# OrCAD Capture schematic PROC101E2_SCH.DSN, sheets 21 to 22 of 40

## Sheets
21 14.OSPI: size C; title: OSPI
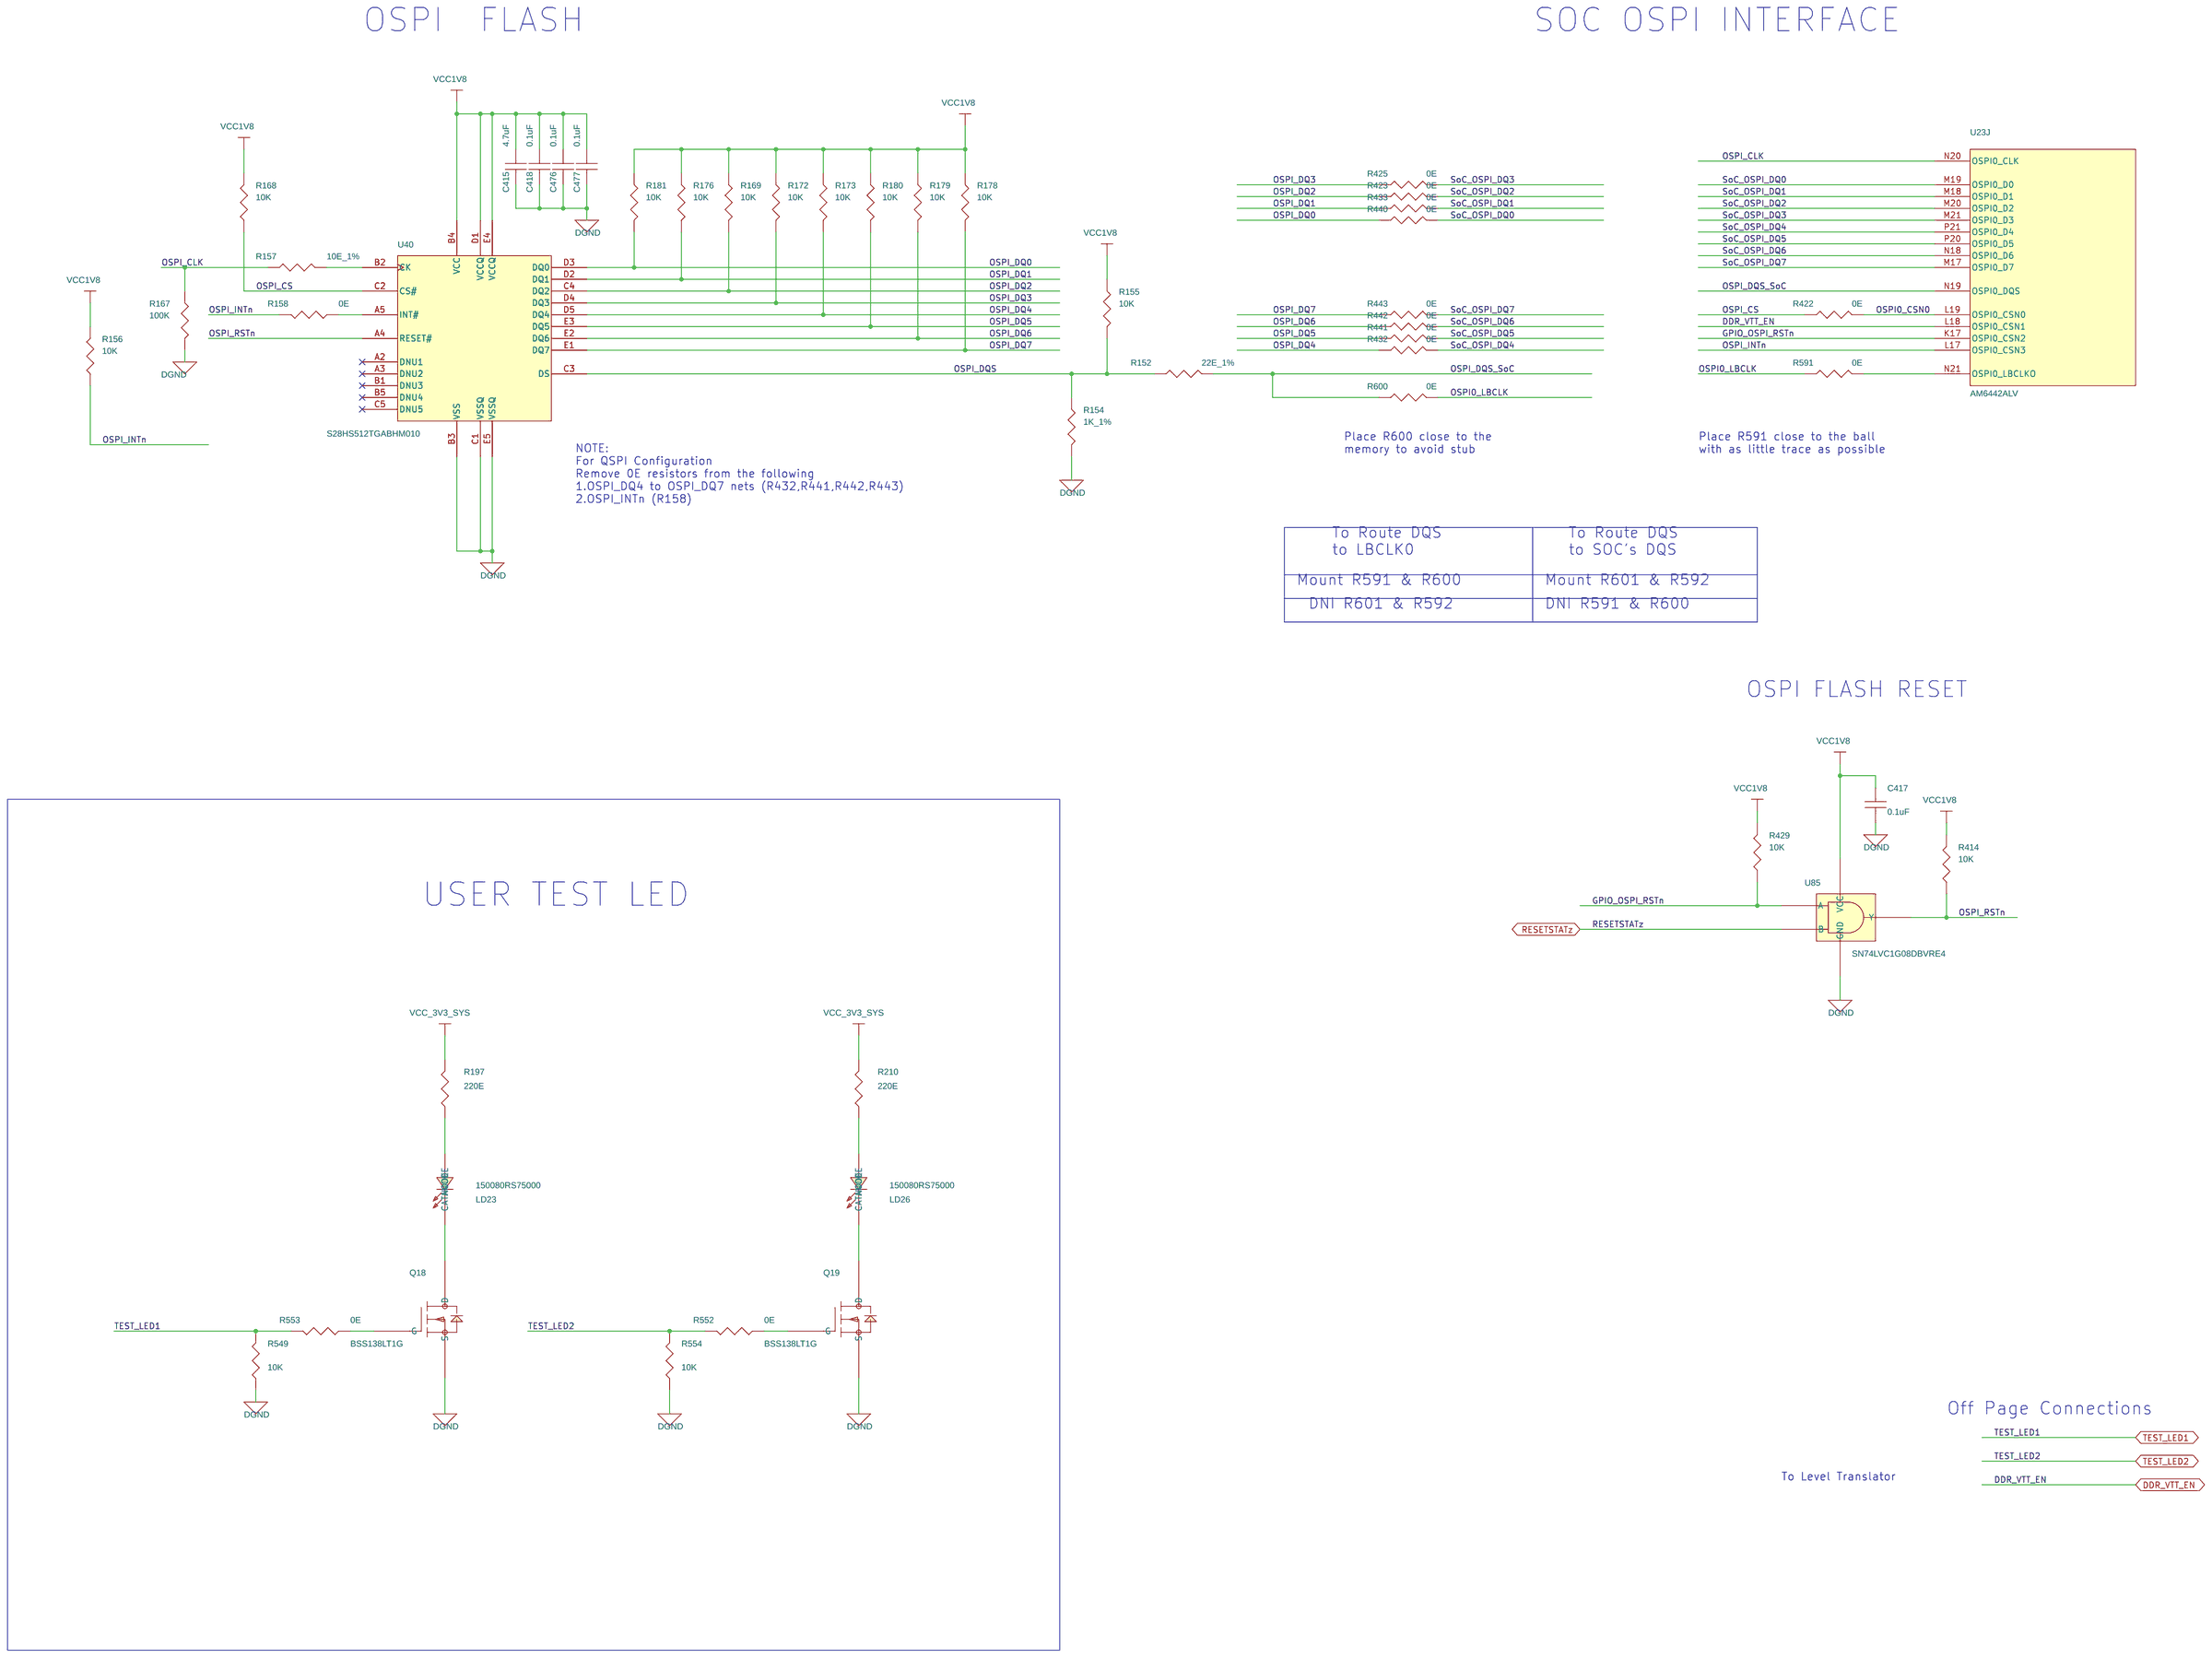
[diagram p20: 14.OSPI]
22 12.DDR INTERFACE: size C; title: DDR INTERFACE
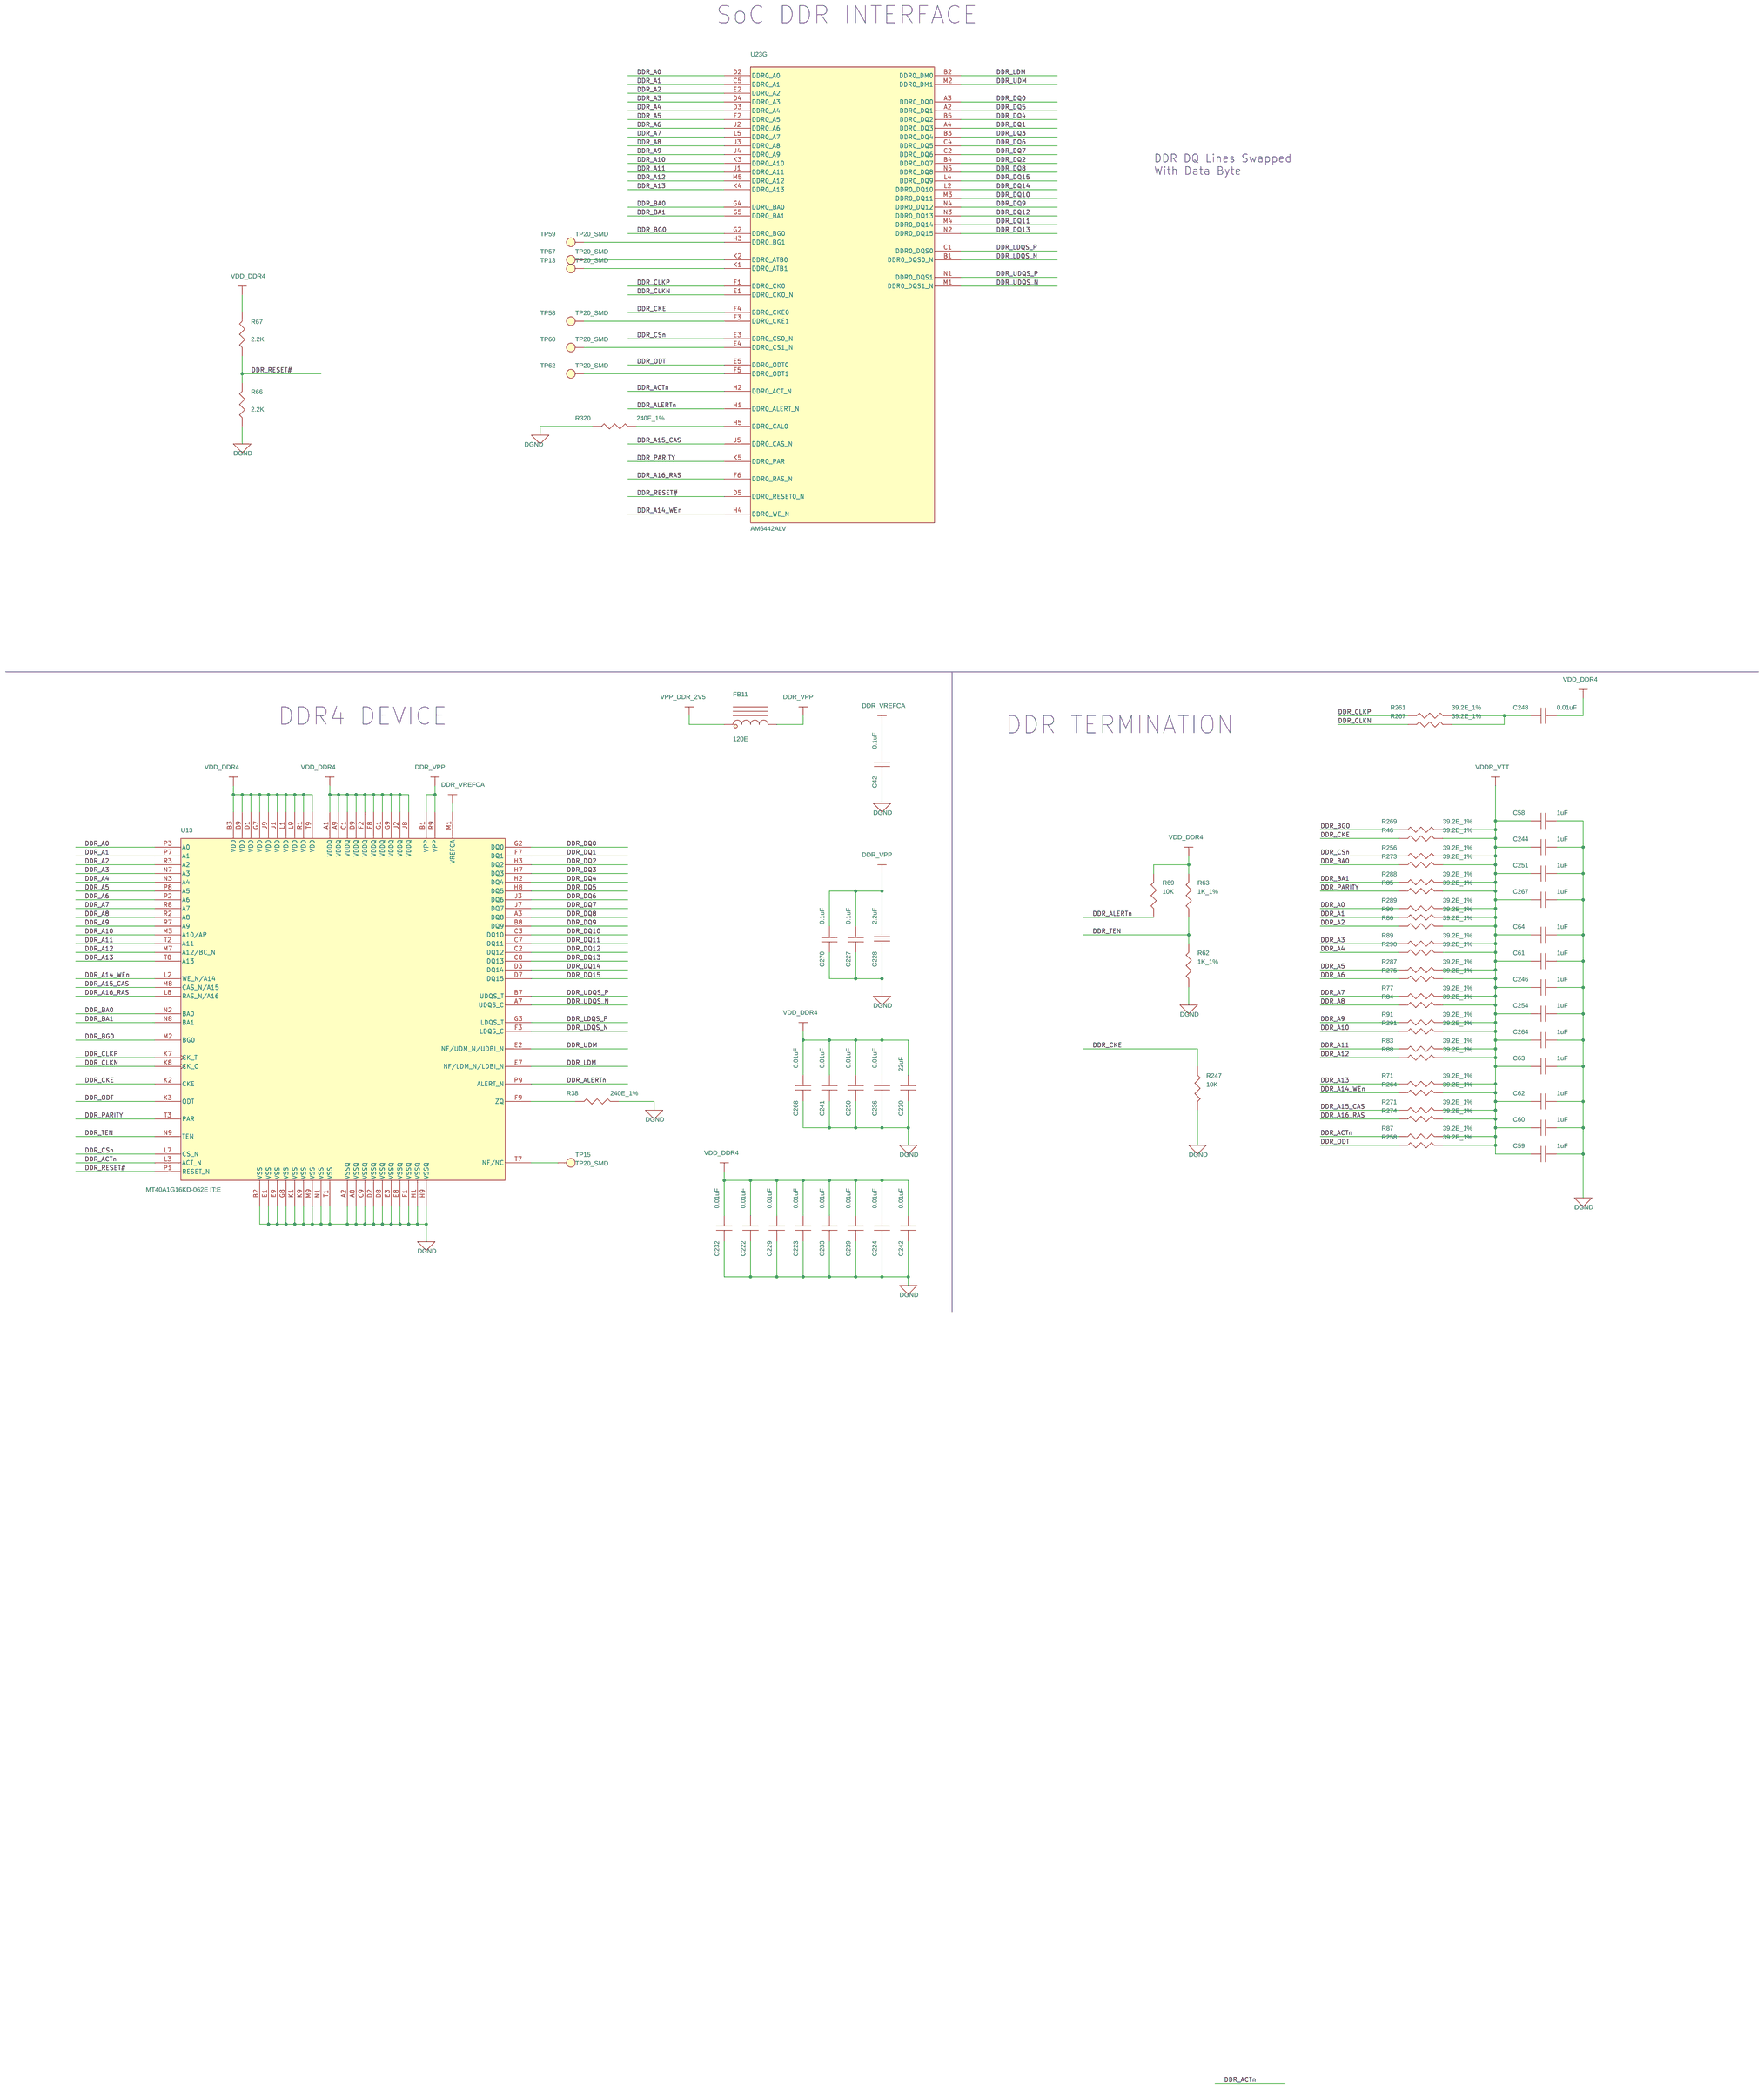
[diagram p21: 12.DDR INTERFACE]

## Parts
sheet 11.SOC VSS
U23  AM6442ALV  [FCBGA441_31-49_680X680_2-6]  (sections A,B,C,D,E,F,G,H,I,J,K,L,M,N,O,P)
sheet 12.DDR INTERFACE
C42  0.1uF  [CAP0201_0-5]
C58  1uF  [CAP0402_0-75]
C59  1uF  [CAP0402_0-75]
C60  1uF  [CAP0402_0-75]
C61  1uF  [CAP0402_0-75]
C62  1uF  [CAP0402_0-75]
C63  1uF  [CAP0402_0-75]
C64  1uF  [CAP0402_0-75]
C222  0.01uF  [CAP0201_0-5]
C223  0.01uF  [CAP0201_0-5]
C224  0.01uF  [CAP0201_0-5]
C227  0.1uF  [CAP0201_0-5]
C228  2.2uF  [CAP0402_0-75]
C229  0.01uF  [CAP0201_0-5]
C230  22uF  [CAP0603_1]
C232  0.01uF  [CAP0201_0-5]
C233  0.01uF  [CAP0201_0-5]
C236  0.01uF  [CAP0201_0-5]
C239  0.01uF  [CAP0201_0-5]
C241  0.01uF  [CAP0201_0-5]
C242  0.01uF  [CAP0201_0-5]
C244  1uF  [CAP0402_0-75]
C246  1uF  [CAP0402_0-75]
C248  0.01uF  [CAP0201_0-5]
C250  0.01uF  [CAP0201_0-5]
C251  1uF  [CAP0402_0-75]
C254  1uF  [CAP0402_0-75]
C264  1uF  [CAP0402_0-75]
C267  1uF  [CAP0402_0-75]
C268  0.01uF  [CAP0201_0-5]
C270  0.1uF  [CAP0201_0-5]
FB11  120E  [IND0603_1]
R38  240E_1%  [RES0402_0-5]
R46  39.2E_1%  [RES0402_0-5]
R62  1K_1%  [RES0402_0-5]
R63  1K_1%  [RES0402_0-5]
R66  2.2K  [RES0402_0-5]
R67  2.2K  [RES0402_0-5]
R69  10K  [RES0402_0-5]
R71  39.2E_1%  [RES0402_0-5]
R77  39.2E_1%  [RES0402_0-5]
R83  39.2E_1%  [RES0402_0-5]
R84  39.2E_1%  [RES0402_0-5]
R85  39.2E_1%  [RES0402_0-5]
R86  39.2E_1%  [RES0402_0-5]
R87  39.2E_1%  [RES0402_0-5]
R88  39.2E_1%  [RES0402_0-5]
R89  39.2E_1%  [RES0402_0-5]
R90  39.2E_1%  [RES0402_0-5]
R91  39.2E_1%  [RES0402_0-5]
R247  10K  [RES0402_0-5]
R256  39.2E_1%  [RES0402_0-5]
R258  39.2E_1%  [RES0402_0-5]
R261  39.2E_1%  [RES0402_0-5]
R264  39.2E_1%  [RES0402_0-5]
R267  39.2E_1%  [RES0402_0-5]
R269  39.2E_1%  [RES0402_0-5]
R271  39.2E_1%  [RES0402_0-5]
R273  39.2E_1%  [RES0402_0-5]
R274  39.2E_1%  [RES0402_0-5]
R275  39.2E_1%  [RES0402_0-5]
R287  39.2E_1%  [RES0402_0-5]
R288  39.2E_1%  [RES0402_0-5]
R289  39.2E_1%  [RES0402_0-5]
R290  39.2E_1%  [RES0402_0-5]
R291  39.2E_1%  [RES0402_0-5]
R320  240E_1%  [RES0402_0-5]
TP13  TP20_SMD  [TP20_SMD]
TP15  TP20_SMD  [TP20_SMD]
TP57  TP20_SMD  [TP20_SMD]
TP58  TP20_SMD  [TP20_SMD]
TP59  TP20_SMD  [TP20_SMD]
TP60  TP20_SMD  [TP20_SMD]
TP62  TP20_SMD  [TP20_SMD]
U13  MT40A1G16KD-062E IT:E  [FBGA96_31-49_520X360_1-2]
sheet 14.OSPI
C415  4.7uF  [CAP0402_0-75]
C417  0.1uF  [CAP0402_0-75]
C418  0.1uF  [CAP0402_0-75]
C476  0.1uF  [CAP0402_0-75]
C477  0.1uF  [CAP0402_0-75]
LD23  150080RS75000  [LED_150080VS75000_80X50_SMD_0-8]
LD26  150080RS75000  [LED_150080VS75000_80X50_SMD_0-8]
Q18  BSS138LT1G  [SOT23-123_1-2]
Q19  BSS138LT1G  [SOT23-123_1-2]
R152  22E_1%  [RES0402_0-5]
R154  1K_1%  [RES0402_0-5]
R155  10K  [RES0402_0-5]
R156  10K  [RES0402_0-5]
R157  10E_1%  [RES0402_0-5]
R158  0E  [RES0402_0-5]
R167  100K  [RES0402_0-5]
R168  10K  [RES0402_0-5]
R169  10K  [RES0402_0-5]
R172  10K  [RES0402_0-5]
R173  10K  [RES0402_0-5]
R176  10K  [RES0402_0-5]
R178  10K  [RES0402_0-5]
R179  10K  [RES0402_0-5]
R180  10K  [RES0402_0-5]
R181  10K  [RES0402_0-5]
R197  220E  [RES0402_0-5]
R210  220E  [RES0402_0-5]
R414  10K  [RES0402_0-5]
R422  0E  [RES0402_0-5]
R423  0E  [RES0402_0-5]
R425  0E  [RES0402_0-5]
R429  10K  [RES0402_0-5]
R432  0E  [RES0402_0-5]
R433  0E  [RES0402_0-5]
R440  0E  [RES0402_0-5]
R441  0E  [RES0402_0-5]
R442  0E  [RES0402_0-5]
R443  0E  [RES0402_0-5]
R549  10K  [RES0402_0-5]
R552  0E  [RES0402_0-5]
R553  0E  [RES0402_0-5]
R554  10K  [RES0402_0-5]
R591  0E  [RES0402_0-5]
R600  0E  [RES0402_0-5]
U40  S28HS512TGABHM010  [BGA24_39-37_240X310_1]
U85  SN74LVC1G08DBVRE4  [SOT23-5]

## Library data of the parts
U23 = AM64-SVB_BGA441: IC AM64 SoC MICROPROCESSOR BGA441; Chkd/date: MANIRAJA/020520; Crtd /date: ALVY/090420; Custom_Duty: 15%; Customs_HS_Code: 85423100; Distributor_name: NA; Distributor_part_number: NA; Footprint Path: Y:\MIS_DATABASE\Library\ALTIUM_TOOL\PCB_FOOTPRINTS\Altium_Footprint_Lib.PcbLib; Height: 2.57MM; Library Path: Y:\MIS_DATABASE\Library\ALTIUM_TOOL\SCHEMATICS_PARTS\MS_MICROPROCESSOR_Library.schlib; Mfr_name: TEXAS INSTRUMENTS; Mfr_part_number: AM6442ASFGGAALV; Mistral Part No: 141220040002; Package: BGA441; Part_type: ICS\DIGITAL\MICROPROCESSOR; Project: AM64x_SVB BRD; RoHS: NA; Temperature: NA; Tolerance: NA; Voltage: NA; Wattage: NA; Weight: NA; Datasheet: Y:\MIS_DATABASE\DATASHEETS\ICS\DIGITAL\MICROCONTROLLER\AM64-SoC_SVB.PDF
C42 C227 C270 = CAP: CAP CERAMIC 0.1uF 16V 10% X5R 0201; Chkd/date: MANIRAJA/120218; Crtd /date: MANIRAJA/120218; Custom_Duty: 15%; Customs_HS_Code: 85322990; Distributor_name: DIGIKEY; Distributor_part_number: 490-16742-1-ND; Footprint Path: Y:\MIS_DATABASE\Library\ALTIUM_TOOL\PCB_FOOTPRINTS\Altium_Footprint_Lib.PcbLib; Height: 0.33MM; Library Path: Y:\MIS_DATABASE\Library\ALTIUM_TOOL\SCHEMATICS_PARTS\MS_DISCRETE_Library.schlib; Mfr_name: MURATA; Mfr_part_number: GRM033R61C104KE84J; Mistral Part No: 120009030072-R; Package: 0201; Part_type: CAPACITORS\CERAMIC; Project: TI_MAXIE_CPB; RoHS: RoHS; Temperature: -55°C+85°C; Tolerance: 10%; Voltage: 16V; Wattage: NA; Weight: 0.33mg; Datasheet: Y:\MIS_DATABASE\DATASHEETS\CAPACITORS\GRM033R61C104KE84.PDF
C58-C64 C244 C246 C251 C254 C264 C267 = CAP: CAP CERAMIC 1uF 10V 20% X5R 0402; Chkd/date: MANIRAJA/210820; Crtd /date: ALVY/190820; Custom_Duty: 15%; Customs_HS_Code: 85322990; Distributor_name: DIGIKEY; Distributor_part_number: 732-7489-1-ND; Footprint Path: Y:\MIS_DATABASE\Library\ALTIUM_TOOL\PCB_FOOTPRINTS\Altium_Footprint_Lib.PcbLib; Height: 0.55MM; Library Path: Y:\MIS_DATABASE\Library\ALTIUM_TOOL\SCHEMATICS_PARTS\MS_DISCRETE_Library.schlib; Mfr_name: WURTH ELECTRONICS; Mfr_part_number: 885012105012; Mistral Part No: 120020080009-R; Package: 0402; Part_type: CAPACITORS\CERAMIC; Project: AM64x_EVM_BRD; RoHS: RoHS; Temperature: -55°C+85°C; Tolerance: 20%; Voltage: 10V; Wattage: NA; Weight: 0.65mg; Datasheet: Y:\MIS_DATABASE\DATASHEETS\CAPACITORS\885012105012.PDF
C222-C224 C229 C232 C233 C236 C239 C241 C242 C248 C250 C268 = CAP: CAP CERAMIC 0.01uF 25V 10% X5R 0201; Chkd/date: MANIRAJA/230118; Crtd /date: MANIRAJA/230118; Custom_Duty: 15%; Customs_HS_Code: 85322990; Distributor_name: DIGIKEY; Distributor_part_number: GRM033R61E103KA12J-ND; Footprint Path: Y:\MIS_DATABASE\Library\ALTIUM_TOOL\PCB_FOOTPRINTS\Altium_Footprint_Lib.PcbLib; Height: 0.33MM; Library Path: Y:\MIS_DATABASE\Library\ALTIUM_TOOL\SCHEMATICS_PARTS\MS_DISCRETE_Library.schlib; Mfr_name: MURATA; Mfr_part_number: GRM033R61E103KA12J; Mistral Part No: 120018010007-R; Package: 0201; Part_type: CAPACITORS\CERAMIC; Project: TI_MAXIE_CPB; RoHS: RoHS; Temperature: -55°C+85°C; Tolerance: 10%; Voltage: 25V; Wattage: NA; Weight: 0.33mg; Datasheet: Y:\MIS_DATABASE\DATASHEETS\CAPACITORS\GRM033R61E103KA12.PDF
C228 = CAP: CAP CERAMIC 2.2uF 10V 20% X5R 0402; Chkd/date: MANIRAJA/170820; Crtd /date: ALVY/170820; Custom_Duty: 15%; Customs_HS_Code: 85322990; Distributor_name: DIGIKEY; Distributor_part_number: 732-7490-1-ND; Footprint Path: Y:\MIS_DATABASE\Library\ALTIUM_TOOL\PCB_FOOTPRINTS\Altium_Footprint_Lib.PcbLib; Height: 0.55MM; Library Path: Y:\MIS_DATABASE\Library\ALTIUM_TOOL\SCHEMATICS_PARTS\MS_DISCRETE_Library.schlib; Mfr_name: WURTH ELECTRONICS; Mfr_part_number: 885012105013; Mistral Part No: 120019040036-R; Package: 0402; Part_type: CAPACITORS\CERAMIC; Project: AM64x_EVM_BRD; RoHS: RoHS; Temperature: -55°C+85°C; Tolerance: 20%; Voltage: 10V; Wattage: NA; Weight: 0.65mg; Datasheet: Y:\MIS_DATABASE\DATASHEETS\CAPACITORS\885012105013.PDF
C230 = CAP: CAP CERAMIC 22uF 6.3V 20% X5R 0603; Chkd/date: JEBRAN/090915; Crtd /date: JEBRAN/090915; Custom_Duty: 15%; Customs_HS_Code: 85322990; Distributor_name: DIGIKEY; Distributor_part_number: 490-7611-2-ND; Footprint Path: Y:\MIS_DATABASE\Library\ALTIUM_TOOL\PCB_FOOTPRINTS\Altium_Footprint_Lib.PcbLib; Height: 1.00MM; Library Path: Y:\MIS_DATABASE\Library\ALTIUM_TOOL\SCHEMATICS_PARTS\MS_DISCRETE_Library.schlib; Mfr_name: MURATA; Mfr_part_number: GRM188R60J226MEA0; Mistral Part No: 120015090007-R; Package: 0603; Part_type: CAPACITORS\CERAMIC; Project: OCTBTS_3000; RoHS: RoHS; Temperature: -55°C+85°C; Tolerance: 20%; Voltage: 6.3V; Wattage: NA; Weight: 6.3mg; Datasheet: Y:\MIS_DATABASE\DATASHEETS\CAPACITORS\MURATA-GXX-SER_NOV17.PDF
FB11 = INDUCTOR_FERRITE: IND FERRITE BEAD CHIP 120E 2A 0603; Chkd/date: MANIRAJA/180820; Crtd /date: ALVY/180820; Custom_Duty: 24%; Customs_HS_Code: 85437099; Distributor_name: DIGIKEY; Distributor_part_number: 732-782631141CT-ND; Footprint Path: Y:\MIS_DATABASE\Library\ALTIUM_TOOL\PCB_FOOTPRINTS\Altium_Footprint_Lib.PcbLib; Height: 1.00MM; Library Path: Y:\MIS_DATABASE\Library\ALTIUM_TOOL\SCHEMATICS_PARTS\MS_FILTER_Library.schlib; Mfr_name: WURTH ELECTRONICS; Mfr_part_number: 782631141; Mistral Part No: 130020080015-R; Package: 0603; Part_type: INDUCTOR; Project: AM64x_EVM_BRD; RoHS: RoHS; Temperature: -55°C+125°C; Tolerance: 25%; Voltage: NA; Wattage: NA; Weight: NA; Datasheet: Y:\MIS_DATABASE\DATASHEETS\DISCRETES\INDUCTORS\782631141.PDF
R38 R320 = RESISTOR: RES 240E 1/10W 1% 0402; Chkd/date: MAZHAR/150611; Crtd /date: BAVISH/020611; Custom_Duty: 15%; Customs_HS_Code: 85332119; Distributor_name: DIGIKEY; Distributor_part_number: P240LCT-ND; Footprint Path: Y:\MIS_DATABASE\Library\ALTIUM_TOOL\PCB_FOOTPRINTS\Altium_Footprint_Lib.PcbLib; Height: 0.40MM; Library Path: Y:\MIS_DATABASE\Library\ALTIUM_TOOL\SCHEMATICS_PARTS\MS_DISCRETE_Library.schlib; Mfr_name: PANASONIC-ECG; Mfr_part_number: ERJ-2RKF2400X; Mistral Part No: 110011060017-R; Package: 0402; Part_type: RESISTORS\FIXED; Project: AM4515_EVM_LCD; RoHS: RoHS; Temperature: -55°C+155°C; Tolerance: 1%; Voltage: NA; Wattage: 1/10W; Weight: 0.8mg; Datasheet: Y:\MIS_DATABASE\DATASHEETS\RESISTORS\PAN-ERJSER_NOV17.PDF
R46 R71 R77 R83-R91 R256 R258 R261 R264 R267 R269 R271 R273-R275 R287-R291 = RESISTOR: RES 39.2E 1/16W 1% 0402; Chkd/date: RAGESH/210411; Crtd /date: MAZHAR/210411; Custom_Duty: 15%; Customs_HS_Code: 85332119; Distributor_name: DIGIKEY; Distributor_part_number: RMCF0402FT39R2CT-ND; Footprint Path: Y:\MIS_DATABASE\Library\ALTIUM_TOOL\PCB_FOOTPRINTS\Altium_Footprint_Lib.PcbLib; Height: 0.40MM; Library Path: Y:\MIS_DATABASE\Library\ALTIUM_TOOL\SCHEMATICS_PARTS\MS_DISCRETE_Library.schlib; Mfr_name: STACKPOLE ELECTRONICS; Mfr_part_number: RMCF0402FT39R2; Mistral Part No: 110011040030-R; Package: 0402; Part_type: RESISTORS\FIXED; Project: AOD_POD-BASECARD; RoHS: RoHS; Temperature: -55°C+155°C; Tolerance: 1%; Voltage: NA; Wattage: 1/16W; Weight: 0.57mg; Datasheet: Y:\MIS_DATABASE\DATASHEETS\RESISTORS\RMCF-SER_JUL18.PDF
R62 R154 = RESISTOR: RES 1K 1/10W 1% 0402; Chkd/date: VASANTHA/281216; Crtd /date: MAZHAR/150506; Custom_Duty: 15%; Customs_HS_Code: 85332119; Distributor_name: DIGIKEY; Distributor_part_number: P1.00KLCT-ND; Footprint Path: Y:\MIS_DATABASE\Library\ALTIUM_TOOL\PCB_FOOTPRINTS\Altium_Footprint_Lib.PcbLib; Height: 0.40MM; Library Path: Y:\MIS_DATABASE\Library\ALTIUM_TOOL\SCHEMATICS_PARTS\MS_DISCRETE_Library.schlib; Mfr_name: PANASONIC-ECG; Mfr_part_number: ERJ-2RKF1001X; Mistral Part No: 110009030411-R; Package: 0402; Part_type: RESISTORS\FIXED; Project: VOCERA; RoHS: RoHS; Temperature: -55°C+155°C; Tolerance: 1%; Voltage: NA; Wattage: 1/10W; Weight: 0.8mg; Datasheet: Y:\MIS_DATABASE\DATASHEETS\RESISTORS\PAN-ERJSER_NOV17.PDF
R63 = RESISTOR: RES 1K 1/10W 1% 0402; Assembly: DNI; Chkd/date: VASANTHA/281216; Crtd /date: MAZHAR/150506; Custom_Duty: 15%; Customs_HS_Code: 85332119; Distributor_name: DIGIKEY; Distributor_part_number: P1.00KLCT-ND; Footprint Path: Y:\MIS_DATABASE\Library\ALTIUM_TOOL\PCB_FOOTPRINTS\Altium_Footprint_Lib.PcbLib; Height: 0.40MM; Library Path: Y:\MIS_DATABASE\Library\ALTIUM_TOOL\SCHEMATICS_PARTS\MS_DISCRETE_Library.schlib; Mfr_name: PANASONIC-ECG; Mfr_part_number: ERJ-2RKF1001X; Mistral Part No: 110009030411-R; Package: 0402; Part_type: RESISTORS\FIXED; Project: VOCERA; RoHS: RoHS; Temperature: -55°C+155°C; Tolerance: 1%; Voltage: NA; Wattage: 1/10W; Weight: 0.8mg; Datasheet: Y:\MIS_DATABASE\DATASHEETS\RESISTORS\PAN-ERJSER_NOV17.PDF
R66 = RESISTOR: RES 2.2K 1/16W 5% 0402; Assembly: DNI; Chkd/date: VASANTHA/061216; Crtd /date: BAVISH/021210; Custom_Duty: 15%; Customs_HS_Code: 85332119; Distributor_name: DIGIKEY; Distributor_part_number: 311-2.2KJRCT-ND; Footprint Path: Y:\MIS_DATABASE\Library\ALTIUM_TOOL\PCB_FOOTPRINTS\Altium_Footprint_Lib.PcbLib; Height: 0.40MM; Library Path: Y:\MIS_DATABASE\Library\ALTIUM_TOOL\SCHEMATICS_PARTS\MS_DISCRETE_Library.schlib; Mfr_name: YAGEO AMERICA; Mfr_part_number: RC0402JR-072K2L; Mistral Part No: 110010120018-R; Package: 0402; Part_type: RESISTORS\FIXED; Project: TE4; RoHS: RoHS; Temperature: -55°C+155°C; Tolerance: 5%; Voltage: NA; Wattage: 1/16W; Weight: 0.65mg; Datasheet: Y:\MIS_DATABASE\DATASHEETS\RESISTORS\RCXXXXL-SER_MAR18.PDF
R67 = RESISTOR: RES 2.2K 1/16W 5% 0402; Chkd/date: VASANTHA/061216; Crtd /date: BAVISH/021210; Custom_Duty: 15%; Customs_HS_Code: 85332119; Distributor_name: DIGIKEY; Distributor_part_number: 311-2.2KJRCT-ND; Footprint Path: Y:\MIS_DATABASE\Library\ALTIUM_TOOL\PCB_FOOTPRINTS\Altium_Footprint_Lib.PcbLib; Height: 0.40MM; Library Path: Y:\MIS_DATABASE\Library\ALTIUM_TOOL\SCHEMATICS_PARTS\MS_DISCRETE_Library.schlib; Mfr_name: YAGEO AMERICA; Mfr_part_number: RC0402JR-072K2L; Mistral Part No: 110010120018-R; Package: 0402; Part_type: RESISTORS\FIXED; Project: TE4; RoHS: RoHS; Temperature: -55°C+155°C; Tolerance: 5%; Voltage: NA; Wattage: 1/16W; Weight: 0.65mg; Datasheet: Y:\MIS_DATABASE\DATASHEETS\RESISTORS\RCXXXXL-SER_MAR18.PDF
R69 R156 R168 R414 R429 R549 R554 = RESISTOR: RES 10K 1/16W 5% 0402; Chkd/date: VASANTHA/061216; Crtd /date: MAZHAR/230805; Custom_Duty: 15%; Customs_HS_Code: 85332119; Distributor_name: DIGIKEY; Distributor_part_number: 311-10KJRCT-ND; Footprint Path: Y:\MIS_DATABASE\Library\ALTIUM_TOOL\PCB_FOOTPRINTS\Altium_Footprint_Lib.PcbLib; Height: 0.40MM; Library Path: Y:\MIS_DATABASE\Library\ALTIUM_TOOL\SCHEMATICS_PARTS\MS_DISCRETE_Library.schlib; Mfr_name: YAGEO AMERICA; Mfr_part_number: RC0402JR-0710KL; Mistral Part No: 110011060021-R; Package: 0402; Part_type: RESISTORS\FIXED; Project: HSE; RoHS: RoHS; Temperature: -55°C+155°C; Tolerance: 5%; Voltage: NA; Wattage: 1/16W; Weight: 0.65mg; Datasheet: Y:\MIS_DATABASE\DATASHEETS\RESISTORS\RCXXXXL-SER_MAR18.PDF
R155 R169 R172 R173 R176 R178-R181 R247 = RESISTOR: RES 10K 1/16W 5% 0402; Assembly: DNI; Chkd/date: VASANTHA/061216; Crtd /date: MAZHAR/230805; Custom_Duty: 15%; Customs_HS_Code: 85332119; Distributor_name: DIGIKEY; Distributor_part_number: 311-10KJRCT-ND; Footprint Path: Y:\MIS_DATABASE\Library\ALTIUM_TOOL\PCB_FOOTPRINTS\Altium_Footprint_Lib.PcbLib; Height: 0.40MM; Library Path: Y:\MIS_DATABASE\Library\ALTIUM_TOOL\SCHEMATICS_PARTS\MS_DISCRETE_Library.schlib; Mfr_name: YAGEO AMERICA; Mfr_part_number: RC0402JR-0710KL; Mistral Part No: 110011060021-R; Package: 0402; Part_type: RESISTORS\FIXED; Project: HSE; RoHS: RoHS; Temperature: -55°C+155°C; Tolerance: 5%; Voltage: NA; Wattage: 1/16W; Weight: 0.65mg; Datasheet: Y:\MIS_DATABASE\DATASHEETS\RESISTORS\RCXXXXL-SER_MAR18.PDF
TP13 TP15 TP57-TP60 TP62 = TESTPOINT: TESTPOINT CIR 20 SMD; Chkd/date: SHREESHAIL/171006; Crtd /date: MAZHAR/171006; Custom_Duty: NA; Customs_HS_Code: NA; Distributor_name: NA; Distributor_part_number: NA; Footprint Path: Y:\MIS_DATABASE\Library\ALTIUM_TOOL\PCB_FOOTPRINTS\Altium_Footprint_Lib.PcbLib; Height: NA; Library Path: Y:\MIS_DATABASE\Library\ALTIUM_TOOL\SCHEMATICS_PARTS\MS_DISCRETE_Library.schlib; MECHANICAL 3D STEP FILE: NA; Mfr_name: LOCAL; Mistral Part No: NA; Package: SMD; Project: BT MODULE_CSRBC04; RoHS: NA; Temperature: NA; Tolerance: NA; Voltage: NA; Wattage: NA; Weight: NA; Datasheet: NA
U13 = MT40A512M16LY_FBGA96: IC 16Gb DDR4 SDRAM FBGA96; Chkd/date: MANIRAJA/280820; Crtd /date: ALVY/280820; Custom_Duty: 15%; Customs_HS_Code: 85423100; Distributor_name: MOUSER; Distributor_part_number: 340-457244-TRAY; Footprint Path: Y:\MIS_DATABASE\Library\ALTIUM_TOOL\PCB_FOOTPRINTS\Altium_Footprint_Lib.PcbLib; Height: 1.20MM; Library Path: Y:\MIS_DATABASE\Library\ALTIUM_TOOL\SCHEMATICS_PARTS\MS_MISCMEMORY_Library.schlib; Mfr_name: MICRON; Mistral Part No: 141120080005-R; Package: FBGA96; Part_type: ICS\DIGITAL\MEMORY; Project: AM64x_EVM_BRD; RoHS: RoHS; Temperature: -40°C+95°C; Tolerance: NA; Voltage: NA; Wattage: NA; Weight: NA; Datasheet: Y:\MIS_DATABASE\DATASHEETS\ICS\MEMORY\MT40A-SER.PDF
C415 = CAP: CAP CERAMIC 4.7uF 10V 20% X5R 0402; Chkd/date: MANIRAJA/230118; Crtd /date: MANIRAJA/230118; Custom_Duty: 15%; Customs_HS_Code: 85322990; Distributor_name: DIGIKEY; Distributor_part_number: 478-10791-1-ND; Footprint Path: Y:\MIS_DATABASE\Library\ALTIUM_TOOL\PCB_FOOTPRINTS\Altium_Footprint_Lib.PcbLib; Height: 0.71MM; Library Path: Y:\MIS_DATABASE\Library\ALTIUM_TOOL\SCHEMATICS_PARTS\MS_DISCRETE_Library.schlib; Mfr_name: AVX CORPORATION; Mfr_part_number: 0402ZD475MAT2A; Mistral Part No: 120012060002-R; Package: 0402; Part_type: CAPACITORS\CERAMIC; Project: TI_MAXIE_CPB; RoHS: RoHS; Temperature: -55°C+85°C; Tolerance: 20%; Voltage: 10V; Wattage: NA; Weight: 0.65mg; Datasheet: Y:\MIS_DATABASE\DATASHEETS\CAPACITORS\AVX_MLC.PDF
C417 C418 C476 C477 = CAP: CAP CERAMIC 0.1uF 25V 20% X5R 0402; Alt_Mfr_name: YAGEO AMERICA; Alt_Mfr_part_number: CC0402KRX5R8BB104; Chkd/date: MANIRAJA/170820; Crtd /date: ALVY/170820; Custom_Duty: 15%; Customs_HS_Code: 85322990; Distributor_name: DIGIKEY; Distributor_part_number: 732-7495-1-ND; Footprint Path: Y:\MIS_DATABASE\Library\ALTIUM_TOOL\PCB_FOOTPRINTS\Altium_Footprint_Lib.PcbLib; Height: 0.55MM; Library Path: Y:\MIS_DATABASE\Library\ALTIUM_TOOL\SCHEMATICS_PARTS\MS_DISCRETE_Library.schlib; Mfr_name: WURTH ELECTRONICS; Mfr_part_number: 885012105018; Mistral Part No: 120020080003-R; Package: 0402; Part_type: CAPACITORS\CERAMIC; Project: AM64x_EVM_BRD; RoHS: RoHS; Temperature: -55°C+85°C; Tolerance: 20%; Voltage: 25V; Wattage: NA; Weight: 0.65mg; Datasheet: Y:\MIS_DATABASE\DATASHEETS\CAPACITORS\885012105018.PDF
LD23 LD26 = DIODE_LED: DIODE LED RED SMD; Chkd/date: MANIRAJA/180820; Crtd /date: ALVY/180820; Custom_Duty: 24%; Customs_HS_Code: 85439000; Distributor_name: DIGIKEY; Distributor_part_number: 732-4984-1-ND; Footprint Path: Y:\MIS_DATABASE\Library\ALTIUM_TOOL\PCB_FOOTPRINTS\Altium_Footprint_Lib.PcbLib; Height: 0.80MM; Library Path: Y:\MIS_DATABASE\Library\ALTIUM_TOOL\SCHEMATICS_PARTS\MS_OPTO_Library.schlib; Mfr_name: WURTH ELECTRONICS; Mistral Part No: 130020080013-R; Package: SMD; Part_type: OPTO\LED; Project: AM64x_EVM_BRD; RoHS: RoHS; Temperature: -40°C+85°C; Tolerance: NA; Voltage: NA; Wattage: NA; Weight: 25mg; Datasheet: Y:\MIS_DATABASE\DATASHEETS\DISCRETES\LEDS\150080RS75000.PDF
Q18 Q19 = MOSFET_BSS138LT1G: IC MOSFET N-CHANNEL 50V 200mA SOT23-3; Chkd/date: MANIRAJA/250219; Crtd /date: JEBRAN/060416; Custom_Duty: 15%; Customs_HS_Code: 85423100; Distributor_name: DIGIKEY; Distributor_part_number: BSS138LT1GOSCT-ND; Footprint Path: Y:\MIS_DATABASE\Library\ALTIUM_TOOL\PCB_FOOTPRINTS\Altium_Footprint_Lib.PcbLib; Height: 1.11MM; Library Path: Y:\MIS_DATABASE\Library\ALTIUM_TOOL\SCHEMATICS_PARTS\MS_MOSFET_Library.schlib; Library Ref: MOSFET_BSS138W; Mfr_name: ON SEMICONDUCTOR; Mistral Part No: 142016040001-R; Package: SOT23-3; Part_type: ICS\POWER\MOSFET; Project: LRDE_ABCM; RoHS: RoHS; Temperature: -55°C+150°C; Tolerance: NA; Voltage: NA; Wattage: NA; Weight: 8mg; Datasheet: Y:\MIS_DATABASE\DATASHEETS\DISCRETES\TRANSISTORS_FETS\BSS138LT1G.PDF
R152 = RESISTOR: RES 22E 1/16W 1% 0402; Chkd/date: SUHAS/290910; Crtd /date: MAZHAR/090909; Cust_part_number: 4700-80047E; Custom_Duty: 15%; Customs_HS_Code: 85332119; Distributor_name: DIGIKEY; Distributor_part_number: 311-22.0LRCT-ND; Footprint Path: Y:\MIS_DATABASE\Library\ALTIUM_TOOL\PCB_FOOTPRINTS\Altium_Footprint_Lib.PcbLib; Height: 0.40MM; Library Path: Y:\MIS_DATABASE\Library\ALTIUM_TOOL\SCHEMATICS_PARTS\MS_DISCRETE_Library.schlib; Mfr_name: YAGEO AMERICA; Mfr_part_number: RC0402FR-0722RL; Mistral Part No: 110009090004-R; Package: 0402; Part_type: RESISTORS\FIXED; Project: VMEFMCD; RoHS: RoHS; SIGNAL_MODEL: RESISTOR_RES0402_22E_22E; Temperature: -55°C+155°C; Tolerance: 1%; Voltage: NA; Wattage: 1/16W; Weight: 0.65mg; Datasheet: Y:\MIS_DATABASE\DATASHEETS\RESISTORS\RCXXXXL-SER_MAR18.PDF
R157 = RESISTOR: RES 10E 1/16W 1% 0402; Chkd/date: MANIRAJA/070218; Crtd /date: ALVY/070218; Custom_Duty: 15%; Customs_HS_Code: 85332119; Distributor_name: DIGIKEY; Distributor_part_number: 311-10.0LRCT-ND; Footprint Path: Y:\MIS_DATABASE\Library\ALTIUM_TOOL\PCB_FOOTPRINTS\Altium_Footprint_Lib.PcbLib; Height: 0.40MM; Library Path: Y:\MIS_DATABASE\Library\ALTIUM_TOOL\SCHEMATICS_PARTS\MS_DISCRETE_Library.schlib; Mfr_name: YAGEO AMERICA; Mfr_part_number: RC0402FR-0710RL; Mistral Part No: 110018020004-R; Package: 0402; Part_type: RESISTORS\FIXED; Project: TI_MAXIE_CPB; RoHS: RoHS; Temperature: -55°C+155°C; Tolerance: 1%; Voltage: NA; Wattage: 1/16W; Weight: 0.65mg; Datasheet: Y:\MIS_DATABASE\DATASHEETS\RESISTORS\RCXXXXL-SER_MAR18.PDF
R158 R422 R423 R425 R432 R433 R440-R443 R552 R553 = RESISTOR: RES 0E 1/16W JUMPER 0402; Chkd/date: VASANTHA/201216; Crtd /date: MUDDU/190810; Custom_Duty: 15%; Customs_HS_Code: 85332119; Distributor_name: DIGIKEY; Distributor_part_number: 541-0.0JCT-ND; Footprint Path: Y:\MIS_DATABASE\Library\ALTIUM_TOOL\PCB_FOOTPRINTS\Altium_Footprint_Lib.PcbLib; Height: 0.40MM; Library Path: Y:\MIS_DATABASE\Library\ALTIUM_TOOL\SCHEMATICS_PARTS\MS_DISCRETE_Library.schlib; Mfr_name: VISHAY; Mfr_part_number: CRCW04020000Z0ED; Mistral Part No: 110010080019-R; Package: 0402; Part_type: RESISTORS\FIXED; Project: PB_BUGBASE; RoHS: RoHS; Temperature: -55°C+155°C; Tolerance: NA; Voltage: NA; Wattage: 1/16W; Weight: 0.65mg; Datasheet: Y:\MIS_DATABASE\DATASHEETS\RESISTORS\CRCW0603.PDF
R167 = RESISTOR: RES 100K 1/16W 5% 0402; Chkd/date: VASANTHA/061216; Crtd /date: BAVISH/010611; Custom_Duty: 15%; Customs_HS_Code: 85332119; Distributor_name: DIGIKEY; Distributor_part_number: 541-100KJCT-ND; Footprint Path: Y:\MIS_DATABASE\Library\ALTIUM_TOOL\PCB_FOOTPRINTS\Altium_Footprint_Lib.PcbLib; Height: 0.40MM; Library Path: Y:\MIS_DATABASE\Library\ALTIUM_TOOL\SCHEMATICS_PARTS\MS_DISCRETE_Library.schlib; Mfr_name: VISHAY; Mfr_part_number: CRCW0402100KJNED; Mistral Part No: 110011060002-R; Package: 0402; Part_type: RESISTORS\FIXED; Project: AM4515_EVM_LCD; RoHS: RoHS; Temperature: -55°C+155°C; Tolerance: 5%; Voltage: NA; Wattage: 1/16W; Weight: 0.65mg; Datasheet: Y:\MIS_DATABASE\DATASHEETS\RESISTORS\CRCW0603.PDF
R197 R210 = RESISTOR: RES 220E 1/10W 5% 0402; Chkd/date: VASANTHA/291216; Crtd /date: GEETHA/260406; Custom_Duty: 15%; Customs_HS_Code: 85332119; Distributor_name: DIGIKEY; Distributor_part_number: P220JCT-ND; Footprint Path: Y:\MIS_DATABASE\Library\ALTIUM_TOOL\PCB_FOOTPRINTS\Altium_Footprint_Lib.PcbLib; Height: 0.40MM; Library Path: Y:\MIS_DATABASE\Library\ALTIUM_TOOL\SCHEMATICS_PARTS\MS_DISCRETE_Library.schlib; Mfr_name: PANASONIC-ECG; Mfr_part_number: ERJ-2GEJ221X; Mistral Part No: 110009030506-R; Package: 0402; Part_type: RESISTORS\FIXED; Project: RED EYE; RoHS: RoHS; Temperature: -55°C+155°C; Tolerance: 5%; Voltage: NA; Wattage: 1/10W; Weight: 0.8mg; Datasheet: Y:\MIS_DATABASE\DATASHEETS\RESISTORS\PAN-ERJSER_NOV17.PDF
R591 R600 = RESISTOR: RES 0E 1/16W JUMPER 0402; Assembly: DNI; Chkd/date: VASANTHA/201216; Crtd /date: MUDDU/190810; Custom_Duty: 15%; Customs_HS_Code: 85332119; Distributor_name: DIGIKEY; Distributor_part_number: 541-0.0JCT-ND; Footprint Path: Y:\MIS_DATABASE\Library\ALTIUM_TOOL\PCB_FOOTPRINTS\Altium_Footprint_Lib.PcbLib; Height: 0.40MM; Library Path: Y:\MIS_DATABASE\Library\ALTIUM_TOOL\SCHEMATICS_PARTS\MS_DISCRETE_Library.schlib; Mfr_name: VISHAY; Mfr_part_number: CRCW04020000Z0ED; Mistral Part No: 110010080019-R; Package: 0402; Part_type: RESISTORS\FIXED; Project: PB_BUGBASE; RoHS: RoHS; Temperature: -55°C+155°C; Tolerance: NA; Voltage: NA; Wattage: 1/16W; Weight: 0.65mg; Datasheet: Y:\MIS_DATABASE\DATASHEETS\RESISTORS\CRCW0603.PDF
U40 = S28HS512T_BGA24: IC 1.8V 512Mb SEMPER FLASH WITH OCTAL INTERFACE BGA24; Chkd/date: MANIRAJA/170120; Crtd /date: ALVY/170120; Custom_Duty: 15%; Customs_HS_Code: 85423100; Distributor_name: NA; Distributor_part_number: NA; Footprint Path: Y:\MIS_DATABASE\Library\ALTIUM_TOOL\PCB_FOOTPRINTS\Altium_Footprint_Lib.PcbLib; Height: 1.00MM; Library Path: Y:\MIS_DATABASE\Library\ALTIUM_TOOL\SCHEMATICS_PARTS\MS_MISCMEMORY_Library.schlib; Mfr_name: CYPRESS SEMICONDUCTOR; Mistral Part No: 141120010002; Package: BGA24; Part_type: ICS\DIGITAL\MEMORY; Project: J7VCL_SOM DUAL LEO PMIC; RoHS: NA; Temperature: -40°C+125°C; Tolerance: NA; Voltage: NA; Wattage: NA; Weight: NA; Datasheet: Y:\MIS_DATABASE\DATASHEETS\ICS\MEMORY\S28HS512T.PDF
U85 = SN74LVC1G08DBVRE4_SOT23-5: IC SINGLE 2-INPUT POSITIVE AND GATE SOT23-5; Chkd/date: SUHAS/221010; Crtd /date: USMAN/151008; Custom_Duty: 15%; Customs_HS_Code: 85423100; Distributor_name: DIGIKEY; Distributor_part_number: SN74LVC1G08DBVRE4-ND; Height: 1.45MM; Mfr_name: TEXAS INSTRUMENTS; Mistral Part No: 141009060026-R; Part_type: ICS\DIGITAL\GATES; Project: KHAN_MAIN; RoHS: Sb/ Br FREE; Temperature: -40°C+85°C; Datasheet: Y:\MIS_DATABASE\DATASHEETS\ICS\DIGITAL\GATES\SN74LVC1G08.PDF

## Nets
DGND: C42.1 C58.2 C59.2 C60.2 C61.2 C62.2 C63.2 C64.2 C222.2 C223.2 C224.2 C227.1 C228.2 C229.2 C230.2 C232.2 C233.2 C236.2 C239.2 C241.2 C242.2 C244.2 C246.2 C250.2 C251.2 C254.2 C264.2 C267.2 C268.2 C270.1 C415.2 C417.2 C418.2 C476.2 C477.2 Q18.2(S) Q19.2(S) R38.2 R62.1 R66.1 R154.2 R167.2 R247.2 R320.2 R549.1 R554.1 U13.A2(VSSQ) U13.A8(VSSQ) U13.B2(VSS) U13.C9(VSSQ) U13.D2(VSSQ) U13.D8(VSSQ) U13.E1(VSS) U13.E3(VSSQ) U13.E8(VSSQ) U13.E9(VSS) U13.F1(VSSQ) U13.G8(VSS) U13.H1(VSSQ) U13.H9(VSSQ) U13.K1(VSS) U13.K9(VSS) U13.M9(VSS) U13.N1(VSS) U13.T1(VSS) U40.B3(VSS) U40.C1(VSSQ) U40.E5(VSSQ) U85.3(GND) ; also on sheet 2 3 4 5 6 7 8 9 10 11 12 13 14 15 16 17 18 19 20 23 24 25 26 27 28 29 30 39 40
VCC1V8: C415.1 C417.1 C418.1 C476.1 C477.1 R155.1 R156.2 R168.2 R169.1 R172.1 R173.1 R176.1 R178.1 R179.1 R180.1 R181.1 R414.2 R429.2 U40.B4(VCC) U40.D1(VCCQ) U40.E4(VCCQ) U85.5(VCC) ; also on sheet 11 12 13 14 15 18 24
VCC_3V3_SYS: R197.2 R210.2 ; also on sheet 2 5 6 7 8 10 11 12 13 14 15 16 17 18 19 20 23 24 25 26 27 29 30 39 40
VDD_DDR4: C222.1 C223.1 C224.1 C229.1 C230.1 C232.1 C233.1 C236.1 C239.1 C241.1 C242.1 C248.2 C250.1 C268.1 R63.2 R67.2 R69.2 U13.A1(VDDQ) U13.A9(VDDQ) U13.B3(VDD) U13.B9(VDD) U13.C1(VDDQ) U13.D1(VDD) U13.D9(VDDQ) U13.F2(VDDQ) U13.F8(VDDQ) U13.G1(VDDQ) U13.G7(VDD) U13.G9(VDDQ) U13.J1(VDD) U13.J2(VDDQ) U13.J8(VDDQ) U13.J9(VDD) U13.L1(VDD) U13.L9(VDD) U13.R1(VDD) U13.T9(VDD) ; also on sheet 3 4 14 16
VDDR_VTT: C58.1 C59.1 C60.1 C61.1 C62.1 C63.1 C64.1 C244.1 C246.1 C251.1 C254.1 C264.1 C267.1 R46.2 R71.2 R77.2 R83.2 R84.2 R85.2 R86.2 R87.2 R88.2 R89.2 R90.2 R91.2 R256.2 R258.2 R264.2 R269.2 R271.2 R273.2 R274.2 R275.2 R287.2 R288.2 R289.2 R290.2 R291.2 ; also on sheet 16
DDR_A0: R289.1 U13.P3(A0) U23.D2(DDR0_A0)
DDR_A1: R90.1 U13.P7(A1) U23.C5(DDR0_A1)
DDR_A2: R86.1 U13.R3(A2) U23.E2(DDR0_A2)
DDR_A3: R89.1 U13.N7(A3) U23.D4(DDR0_A3)
DDR_A4: R290.1 U13.N3(A4) U23.D3(DDR0_A4)
DDR_A5: R287.1 U13.P8(A5) U23.F2(DDR0_A5)
DDR_A6: R275.1 U13.P2(A6) U23.J2(DDR0_A6)
DDR_A7: R77.1 U13.R8(A7) U23.L5(DDR0_A7)
DDR_A8: R84.1 U13.R2(A8) U23.J3(DDR0_A8)
DDR_A9: R91.1 U13.R7(A9) U23.J4(DDR0_A9)
DDR_A10: R291.1 U13.M3(A10/AP) U23.K3(DDR0_A10)
DDR_A11: R83.1 U13.T2(A11) U23.J1(DDR0_A11)
DDR_A12: R88.1 U13.M7(A12/BC_N) U23.M5(DDR0_A12)
DDR_A13: R71.1 U13.T8(A13) U23.K4(DDR0_A13)
DDR_A14_WEn: R264.1 U13.L2(WE_N/A14) U23.H4(DDR0_WE_N)
DDR_A15_CAS: R271.1 U13.M8(CAS_N/A15) U23.J5(DDR0_CAS_N)
DDR_A16_RAS: R274.1 U13.L8(RAS_N/A16) U23.F6(DDR0_RAS_N)
DDR_ACTn: R87.1 U13.L3(ACT_N) U23.H2(DDR0_ACT_N)
DDR_ALERTn: R69.1 U13.P9(ALERT_N) U23.H1(DDR0_ALERT_N)
DDR_BA0: R273.1 U13.N2(BA0) U23.G4(DDR0_BA0)
DDR_BA1: R288.1 U13.N8(BA1) U23.G5(DDR0_BA1)
DDR_BG0: R269.1 U13.M2(BG0) U23.G2(DDR0_BG0)
DDR_CKE: R46.1 R247.1 U13.K2(CKE) U23.F4(DDR0_CKE0)
DDR_CLKN: R267.1 U13.K8(CK_C) U23.E1(DDR0_CK0_N)
DDR_CLKP: R261.1 U13.K7(CK_T) U23.F1(DDR0_CK0)
DDR_CSn: R256.1 U13.L7(CS_N) U23.E3(DDR0_CS0_N)
DDR_DQ0: U13.G2(DQ0) U23.A3(DDR0_DQ0)
DDR_DQ1: U13.F7(DQ1) U23.A4(DDR0_DQ3)
DDR_DQ2: U13.H3(DQ2) U23.B4(DDR0_DQ7)
DDR_DQ3: U13.H7(DQ3) U23.B3(DDR0_DQ4)
DDR_DQ4: U13.H2(DQ4) U23.B5(DDR0_DQ2)
DDR_DQ5: U13.H8(DQ5) U23.A2(DDR0_DQ1)
DDR_DQ6: U13.J3(DQ6) U23.C4(DDR0_DQ5)
DDR_DQ7: U13.J7(DQ7) U23.C2(DDR0_DQ6)
DDR_DQ8: U13.A3(DQ8) U23.N5(DDR0_DQ8)
DDR_DQ9: U13.B8(DQ9) U23.N4(DDR0_DQ12)
DDR_DQ10: U13.C3(DQ10) U23.M3(DDR0_DQ11)
DDR_DQ11: U13.C7(DQ11) U23.M4(DDR0_DQ14)
DDR_DQ12: U13.C2(DQ12) U23.N3(DDR0_DQ13)
DDR_DQ13: U13.C8(DQ13) U23.N2(DDR0_DQ15)
DDR_DQ14: U13.D3(DQ14) U23.L2(DDR0_DQ10)
DDR_DQ15: U13.D7(DQ15) U23.L4(DDR0_DQ9)
DDR_LDM: U13.E7(NF/LDM_N/LDBI_N) U23.B2(DDR0_DM0)
DDR_LDQS_N: U13.F3(LDQS_C) U23.B1(DDR0_DQS0_N)
DDR_LDQS_P: U13.G3(LDQS_T) U23.C1(DDR0_DQS0)
DDR_ODT: R258.1 U13.K3(ODT) U23.E5(DDR0_ODT0)
DDR_PARITY: R85.1 U13.T3(PAR) U23.K5(DDR0_PAR)
DDR_RESET#: R66.2 R67.1 U13.P1(RESET_N) U23.D5(DDR0_RESET0_N)
DDR_TEN: R62.2 R63.1 U13.N9(TEN)
DDR_UDM: U13.E2(NF/UDM_N/UDBI_N) U23.M2(DDR0_DM1)
DDR_UDQS_N: U13.A7(UDQS_C) U23.M1(DDR0_DQS1_N)
DDR_UDQS_P: U13.B7(UDQS_T) U23.N1(DDR0_DQS1)
DDR_VPP: C227.2 C228.1 C270.2 FB11.2 U13.B1(VPP) U13.R9(VPP)
DDR_VREFCA: C42.2 U13.M1(VREFCA) ; also on sheet 16
DDR_VTT_EN: U23.L18(OSPI0_CSN1) ; also on sheet 13
GPIO_OSPI_RSTn: R429.1 U23.K17(OSPI0_CSN2) U85.1(A)
OSPI0_CSN0: R422.2 U23.L19(OSPI0_CSN0)
OSPI0_LBCLK: R591.1 R600.2
OSPI_CLK: R157.1 R167.1 U23.N20(OSPI0_CLK)
OSPI_CS: R168.1 R422.1 U40.C2(CS#)
OSPI_DQ0: R181.2 R440.1 U40.D3(DQ0)
OSPI_DQ1: R176.2 R433.1 U40.D2(DQ1)
OSPI_DQ2: R169.2 R423.1 U40.C4(DQ2)
OSPI_DQ3: R172.2 R425.1 U40.D4(DQ3)
OSPI_DQ4: R173.2 R432.1 U40.D5(DQ4)
OSPI_DQ5: R180.2 R441.1 U40.E3(DQ5)
OSPI_DQ6: R179.2 R442.1 U40.E2(DQ6)
OSPI_DQ7: R178.2 R443.1 U40.E1(DQ7)
OSPI_DQS: R152.1 R154.1 R155.2 U40.C3(DS)
OSPI_DQS_SoC: R152.2 R600.1 U23.N19(OSPI0_DQS)
OSPI_INTn: R156.1 R158.2 U23.L17(OSPI0_CSN3)
OSPI_RSTn: R414.1 U40.A4(RESET#) U85.4(Y)
RESETSTATz: U85.2(B) ; also on sheet 5 12 13 24 29
SoC_OSPI_DQ0: R440.2 U23.M19(OSPI0_D0)
SoC_OSPI_DQ1: R433.2 U23.M18(OSPI0_D1)
SoC_OSPI_DQ2: R423.2 U23.M20(OSPI0_D2)
SoC_OSPI_DQ3: R425.2 U23.M21(OSPI0_D3)
SoC_OSPI_DQ4: R432.2 U23.P21(OSPI0_D4)
SoC_OSPI_DQ5: R441.2 U23.P20(OSPI0_D5)
SoC_OSPI_DQ6: R442.2 U23.N18(OSPI0_D6)
SoC_OSPI_DQ7: R443.2 U23.M17(OSPI0_D7)
TEST_LED1: R549.2 R553.2 ; also on sheet 13
TEST_LED2: R552.2 R554.2 ; also on sheet 12
VPP_DDR_2V5: FB11.1 ; also on sheet 16
N16879988: R38.1 U13.F9(ZQ)
N16880168: TP15.1(TP) U13.T7(NF/NC)
N16887346: R320.1 U23.H5(DDR0_CAL0)
N16887366: TP57.1(TP) U23.K2(DDR0_ATB0)
N16887368: TP13.1(TP) U23.K1(DDR0_ATB1)
N16887377: TP59.1(TP) U23.H3(DDR0_BG1)
N16887386: TP58.1(TP) U23.F3(DDR0_CKE1)
N16887395: TP60.1(TP) U23.E4(DDR0_CS1_N)
N16887404: TP62.1(TP) U23.F5(DDR0_ODT1)
N20753582: C248.1 R261.2 R267.2
N26002209: R157.2 U40.B2(CK)
N26002808: Q19.1(G) R552.1
N26002814: LD26.2(ANODE) R210.1
N26002874: Q18.1(G) R553.1
N26002883: LD23.2(ANODE) R197.1
N26523524: R158.1 U40.A5(INT#)
N28035755: R591.2 U23.N21(OSPI0_LBCLKO)
N28119618: LD23.1(CATHODE) Q18.3(D)
N28119621: LD26.1(CATHODE) Q19.3(D)

Not connected (* = marked no-connect by the designer): U40 A2(DNU1)* A3(DNU2)* B1(DNU3)* B5(DNU4)* C5(DNU5)*

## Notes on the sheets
sheet 21
- OSPI  FLASH
- SOC OSPI INTERFACE
- NOTE:
  For QSPI Configuration
  Remove 0E resistors from the following
  1.OSPI_DQ4 to OSPI_DQ7 nets (R432,R441,R442,R443)
  2.OSPI_INTn (R158)
- Place R600 close to the
  memory to avoid stub
- Place R591 close to the ball
  with as little trace as possible
- To Route DQS
  to LBCLK0
- To Route DQS
  to SOC's DQS
- Mount R591 & R600
- Mount R601 & R592
- DNI R601 & R592
- DNI R591 & R600
- OSPI FLASH RESET
- USER TEST LED
- Off Page Connections
- To Level Translator
sheet 22
- SoC DDR INTERFACE
- DDR DQ Lines Swapped
  With Data Byte
- DDR4 DEVICE
- DDR TERMINATION
